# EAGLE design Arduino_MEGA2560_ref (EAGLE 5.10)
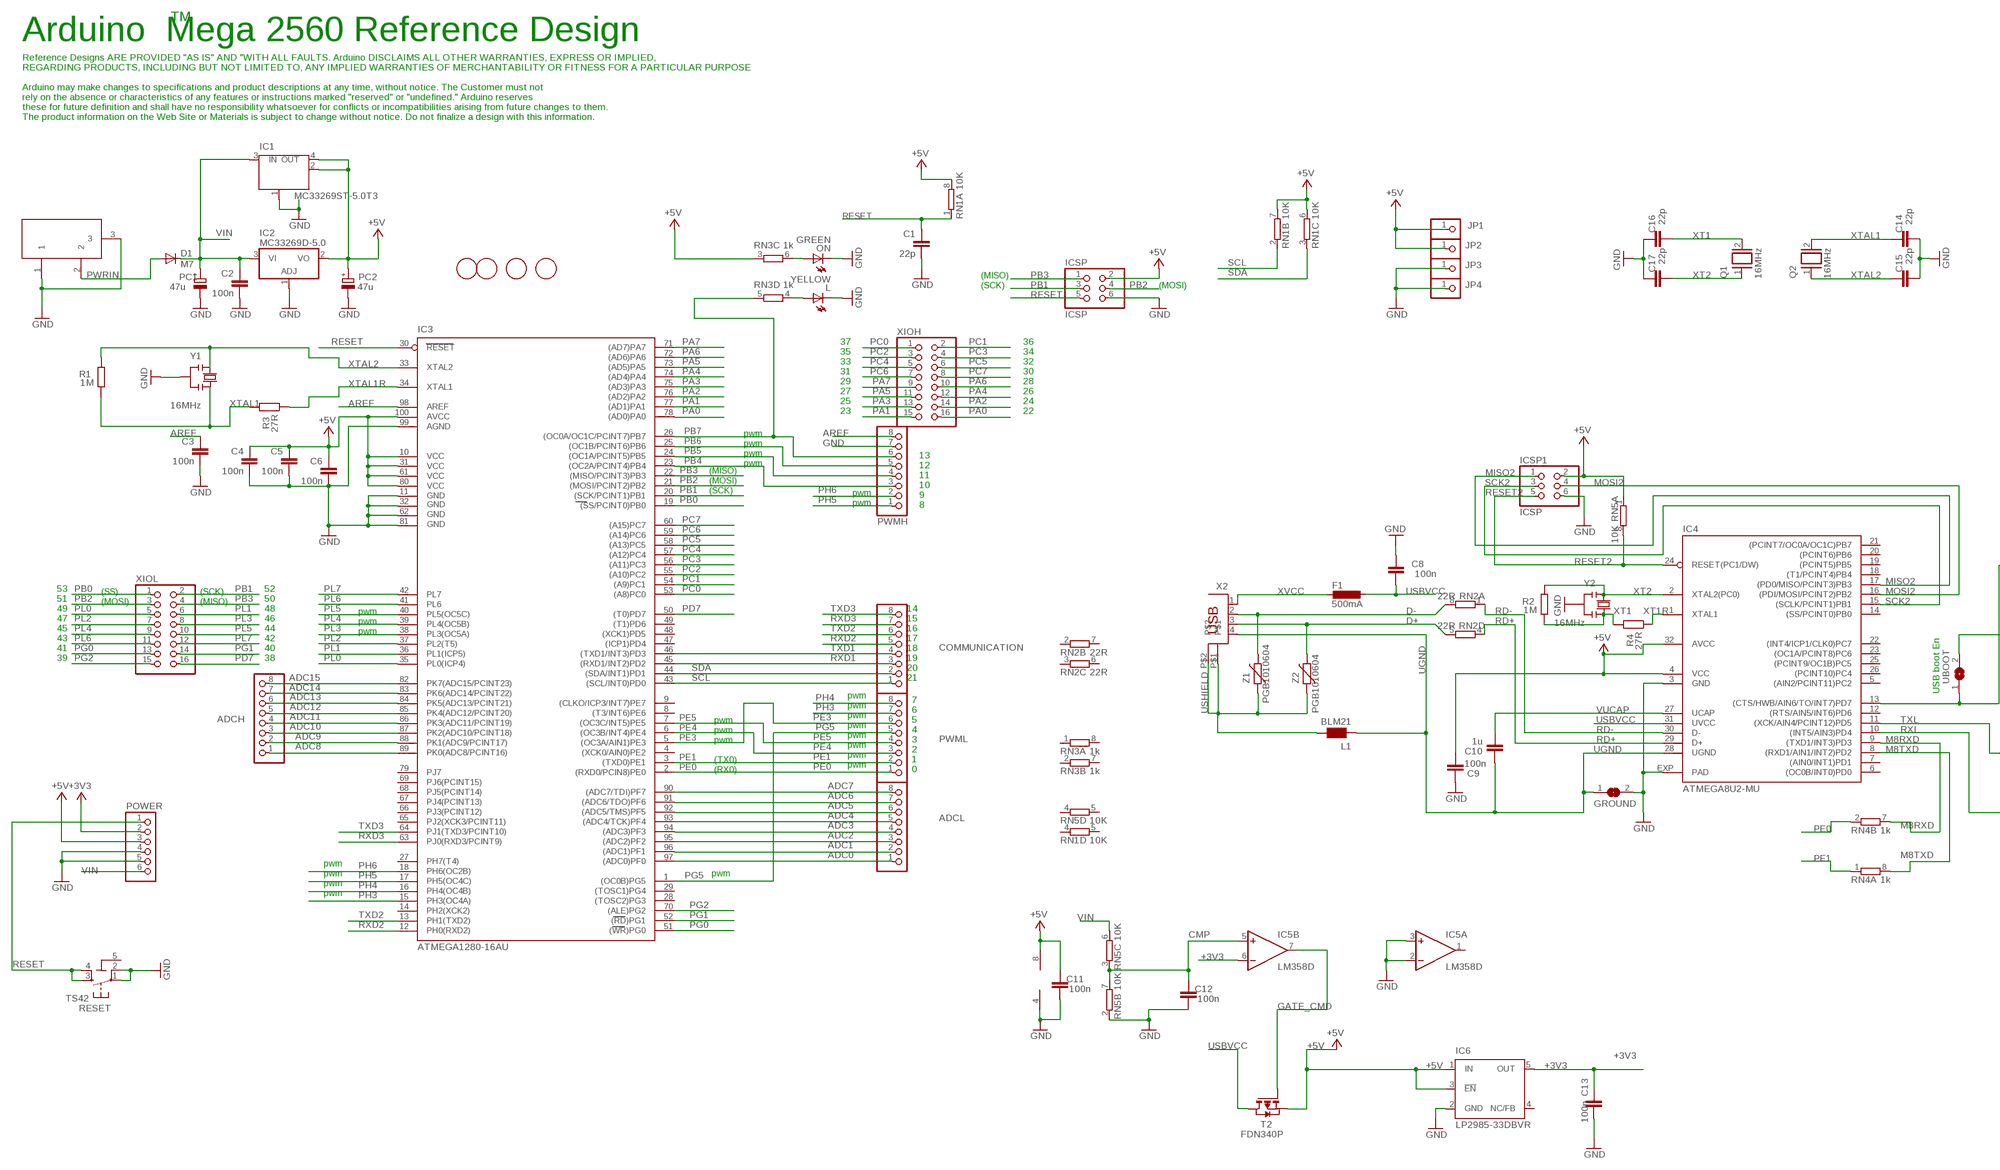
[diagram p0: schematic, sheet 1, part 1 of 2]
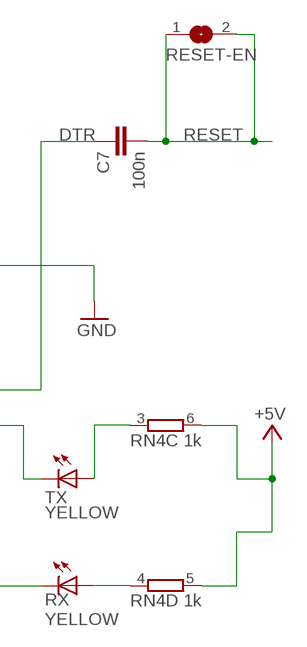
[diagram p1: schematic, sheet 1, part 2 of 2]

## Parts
ADCH  PINHD-1X8  [1X08]
ADCL  PINHD-1X8  [1X08]
C1  22p  C-EU0603-RND  [C0603-ROUND]
C2  100n  C-EU0603-RND  [C0603-ROUND]
C3  100n  C-EU0603-RND  [C0603-ROUND]
C4  100n  C-EU0603-RND  [C0603-ROUND]
C5  100n  C-EU0603-RND  [C0603-ROUND]
C6  100n  C-EU0603-RND  [C0603-ROUND]
C7  100n  C-EU0603-RND  [C0603-ROUND]
C8  100n  C-EUC0603  [C0603]
C9  100n  C-EU0603-RND  [C0603-ROUND]
C10  1u  C-EU0603-RND  [C0603-ROUND]
C11  100n  C-EUC0603  [C0603]
C12  100n  C-EU0603-RND  [C0603-ROUND]
C13  100n  C-EU0603-RND  [C0603-ROUND]
C14  22p  C-EU0603-RND  [C0603-ROUND]
C15  22p  C-EU0603-RND  [C0603-ROUND]
C16  22p  C-EU0603-RND  [C0603-ROUND]
C17  22p  C-EU0603-RND  [C0603-ROUND]
COMMUNICATION  PINHD-1X8  [1X08]
D1  M7  DIODE-SMB  [SMB]
F1  500mA  L-EUL1812  [L1812]
GROUND  SJ  [SJ]
IC1  MC33269ST-5.0T3  MC33269ST-3.3T3  [SOT223]
IC2  MC33269D-5.0  [DPACK]
IC3  ATMEGA1280-16AU  [TQFP100]
IC4  ATMEGA8U2-MU  [QFN32]
IC5  LM358D  [SO08]
IC6  LP2985-33DBVR  TPS77033  [SOT23-DBV]
ICSP  ICSP  PINHD-2X3  [2X03]
ICSP1  ICSP  PINHD-2X3  [2X03]
JP1  PINHD-1X1  [1X01]
JP2  PINHD-1X1  [1X01]
JP3  PINHD-1X1  [1X01]
JP4  PINHD-1X1  [1X01]
L  YELLOW  LEDCHIP-LED0805  [CHIP-LED0805]
L1  BLM21  WE-CBF_0805  [0805]
ON  GREEN  LEDCHIP-LED0805  [CHIP-LED0805]
PC1  47u  CPOL-EUD  [PANASONIC_D]
PC2  47u  CPOL-EUD  [PANASONIC_D]
POWER  PINHD-1X6  [1X06]
PWMH  PINHD-1X8  [1X08]
PWML  PINHD-1X8  [1X08]
Q1  16MHz  XTAL/S  [QS]
Q2  16MHz  XTAL/S  [QS]
R1  1M  R-EU_R0603  [R0603-ROUND]
R2  1M  R-EU_R0603  [R0603-ROUND]
R3  27R  R-EU_R0603  [R0603-ROUND]
R4  27R  R-EU_R0603  [R0603-ROUND]
RESET  TS42  [TS42]
RESET-EN  SJ  [SJ]
RN1  10K  4R-NCAT16  [CAT16]
RN2  22R  4R-NCAY16  [CAY16]
RN3  1k  4R-NCAY16  [CAY16]
RN4  1k  4R-NCAY16  [CAY16]
RN5  10K  4R-NCAT16  [CAT16]
RX  YELLOW  LEDCHIP-LED0805  [CHIP-LED0805]
T2  FDN340P  PMOSSOT23  [SOT-23]
TX  YELLOW  LEDCHIP-LED0805  [CHIP-LED0805]
U$2  FIDUCIALMOUNT  [FIDUCIA-MOUNT]
U$3  FIDUCIALMOUNT  [FIDUCIA-MOUNT]
U$4  FIDUCIALMOUNT  [FIDUCIA-MOUNT]
U$5  FIDUCIALMOUNT  [FIDUCIA-MOUNT]
UBOOT  SJ  [SJ]
X1  DC21MMX  [DC-21MM]
X2  PN61729  [PN61729]
XIOH  PINHD-2X8  [2X08]
XIOL  PINHD-2X8  [2X08]
Y1  16MHz  RESONATORMU  [RESONATOR]
Y2  16MHz  RESONATORMU  [RESONATOR]
Z1  PGB1010604  VARISTORCN0603  [CT/CN0603]
Z2  PGB1010604  VARISTORCN0603  [CT/CN0603]

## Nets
+3V3: C13.2 IC5.6(B:-IN) IC6.5(OUT) POWER.2
+5V: C4.1 C5.1 C6.1 C9.1 C11.2 IC1.2(OUT) IC1.4(OUT) IC2.2(VO) IC3.10(VCC) IC3.31(VCC1) IC3.61(VCC2) IC3.80(VCC3) IC3.100(AVCC) IC4.4(VCC) IC4.32(AVCC) IC5.8(P:V+) IC6.1(IN) IC6.3(!EN) ICSP1.2 ICSP.2 JP1.1 JP2.1 PC2.+ POWER.3 RN1.6 RN1.7 RN1.8 RN3.3 RN4.5 RN4.6 RN5.1 T2.2(S)
ADC0: ADCL.1 IC3.97((ADC0)PF0)
ADC1: ADCL.2 IC3.96((ADC1)PF1)
ADC2: ADCL.3 IC3.95((ADC2)PF2)
ADC3: ADCL.4 IC3.94((ADC3)PF3)
ADC4: ADCL.5 IC3.93((ADC4/TCK)PF4)
ADC5: ADCL.6 IC3.92((ADC5/TMS)PF5)
ADC6: ADCL.7 IC3.91((ADC6/TDO)PF6)
ADC7: ADCL.8 IC3.90((ADC7/TDI)PF7)
ADC8: ADCH.1 IC3.89(PK0(ADC8/PCINT16))
ADC9: ADCH.2 IC3.88(PK1(ADC9/PCINT17))
ADC10: ADCH.3 IC3.87(PK2(ADC10/PCINT18))
ADC11: ADCH.4 IC3.86(PK3(ADC11/PCINT19))
ADC12: ADCH.5 IC3.85(PK4(ADC12/PCINT20))
ADC13: ADCH.6 IC3.84(PK5(ADC13/PCINT21))
ADC14: ADCH.7 IC3.83(PK6(ADC14/PCINT22))
ADC15: ADCH.8 IC3.82(PK7(ADC15/PCINT23))
AREF: C3.1 IC3.98(AREF) PWMH.8
CMP: C12.2 IC5.5(B:+IN) RN5.3 RN5.7
D+: RN2.5 X2.3 Z2.2
D-: RN2.8 X2.2 Z1.2
DTR: C7.1 IC4.13((CTS/HWB/AIN6/TO/INT7)PD7) UBOOT.1
GATE_CMD: IC5.7(B:OUT) T2.3(G)
GND: C1.2 C2.2 C3.2 C4.2 C5.2 C6.2 C8.2 C9.2 C11.1 C12.1 C13.1 C14.1 C15.1 C16.2 C17.2 GROUND.2 IC1.1(GND/ADJ) IC2.1(ADJ) IC3.11(GND) IC3.32(GND1) IC3.62(GND2) IC3.81(GND3) IC3.99(AGND) IC4.3(GND) IC4.EXP(PAD) IC5.2(A:-IN) IC5.3(A:+IN) IC5.4(P:V-) IC6.2(GND) ICSP1.6 ICSP.6 JP3.1 JP4.1 L.C ON.C PC1.- PC2.- POWER.4 POWER.5 PWMH.7 RESET.1 RESET.2 RN5.2 UBOOT.2 X1.1 X1.3 Y1.2 Y2.2
M8RXD: IC4.9((TXD1/INT3)PD3) RN4.7
M8TXD: IC4.8((RXD1/AIN1/INT2)PD2) RN4.8
MISO2: IC4.17((PD0/MISO/PCINT3)PB3) ICSP1.1
MOSI2: IC4.16((PDI/MOSI/PCINT2)PB2) ICSP1.4
N$2: L.A RN3.4
N$3: ON.A RN3.6
N$54: RN4.4 RX.A
N$55: RN4.3 TX.A
PA0: IC3.78((AD0)PA0) XIOH.16
PA1: IC3.77((AD1)PA1) XIOH.15
PA2: IC3.76((AD2)PA2) XIOH.14
PA3: IC3.75((AD3)PA3) XIOH.13
PA4: IC3.74((AD4)PA4) XIOH.12
PA5: IC3.73((AD5)PA5) XIOH.11
PA6: IC3.72((AD6)PA6) XIOH.10
PA7: IC3.71((AD7)PA7) XIOH.9
PB0: IC3.19((SS/PCINT0)PB0) XIOL.1
PB1: IC3.20((SCK/PCINT1)PB1) ICSP.3 XIOL.2
PB2: IC3.21((MOSI/PCINT2)PB2) ICSP.4 XIOL.3
PB3: IC3.22((MISO/PCINT3)PB3) ICSP.1 XIOL.4
PB4: IC3.23((OC2A/PCINT4)PB4) PWMH.3
PB5: IC3.24((OC1A/PCINT5)PB5) PWMH.4
PB6: IC3.25((OC1B/PCINT6)PB6) PWMH.5
PB7: IC3.26((OC0A/OC1C/PCINT7)PB7) PWMH.6 RN3.5
PC0: IC3.53((A8)PC0) XIOH.1
PC1: IC3.54((A9)PC1) XIOH.2
PC2: IC3.55((A10)PC2) XIOH.3
PC3: IC3.56((A11)PC3) XIOH.4
PC4: IC3.57((A12)PC4) XIOH.5
PC5: IC3.58((A13)PC5) XIOH.6
PC6: IC3.59((A14)PC6) XIOH.7
PC7: IC3.60((A15)PC7) XIOH.8
PD7: IC3.50((T0)PD7) XIOL.16
PE0: IC3.2((RXD0/PCIN8)PE0) PWML.1 RN4.2
PE1: IC3.3((TXD0)PE1) PWML.2 RN4.1
PE3: IC3.5((OC3A/AIN1)PE3) PWML.6
PE4: IC3.6((OC3B/INT4)PE4) PWML.3
PE5: IC3.7((OC3C/INT5)PE5) PWML.4
PG0: IC3.51((WR)PG0) XIOL.13
PG1: IC3.52((RD)PG1) XIOL.14
PG2: IC3.70((ALE)PG2) XIOL.15
PG5: IC3.1((OC0B)PG5) PWML.5
PH3: IC3.15(PH3(OC4A)) PWML.7
PH4: IC3.16(PH4(OC4B)) PWML.8
PH5: IC3.17(PH5(OC4C)) PWMH.1
PH6: IC3.18(PH6(OC2B)) PWMH.2
PL0: IC3.35(PL0(ICP4)) XIOL.5
PL1: IC3.36(PL1(ICP5)) XIOL.6
PL2: IC3.37(PL2(T5)) XIOL.7
PL3: IC3.38(PL3(OC5A)) XIOL.8
PL4: IC3.39(PL4(OC5B)) XIOL.9
PL5: IC3.40(PL5(OC5C)) XIOL.10
PL6: IC3.41(PL6) XIOL.11
PL7: IC3.42(PL7) XIOL.12
PWRIN: D1.A X1.2
RD+: IC4.29(D+) RN2.4
RD-: IC4.30(D-) RN2.1
RESET: C1.1 C7.2 IC3.30(RESET) ICSP.5 POWER.1 RESET-EN.1 RESET-EN.2 RESET.3 RESET.4 RN1.1
RESET2: IC4.24(RESET(PC1/DW)) ICSP1.5 RN5.8
RXD1: COMMUNICATION.3 IC3.45((RXD1/INT2)PD2)
RXD2: COMMUNICATION.5 IC3.12(PH0(RXD2))
RXD3: COMMUNICATION.7 IC3.63(PJ0(RXD3/PCINT9))
RXL: IC4.10((INT5/AIN3)PD4) RX.C
SCK2: IC4.15((SCLK/PCINT1)PB1) ICSP1.3
SCL: COMMUNICATION.1 IC3.43((SCL/INT0)PD0) RN1.2
SDA: COMMUNICATION.2 IC3.44((SDA/INT1)PD1) RN1.3
TXD1: COMMUNICATION.4 IC3.46((TXD1/INT3)PD3)
TXD2: COMMUNICATION.6 IC3.13(PH1(TXD2))
TXD3: COMMUNICATION.8 IC3.64(PJ1(TXD3/PCINT10))
TXL: IC4.11((XCK/AIN4/PCINT12)PD5) TX.C
UGND: C10.2 GROUND.1 IC4.28(UGND) L1.1 X2.4
USBVCC: C8.1 F1.1 IC4.31(UVCC) T2.1(D)
USHIELD: L1.2 X2.P$1 X2.P$2 Z1.1 Z2.1
VIN: C2.1 D1.C IC1.3(IN) IC2.3(VI) PC1.+ POWER.6 RN5.6
VUCAP: C10.1 IC4.27(UCAP)
XT1: C16.1 Q1.2 R2.1 R4.2 Y2.3
XT1R: IC4.1(XTAL1) R4.1
XT2: C17.1 IC4.2(XTAL2(PC0)) Q1.1 R2.2 Y2.1
XTAL1: C14.2 Q2.2 R1.1 R3.2 Y1.3
XTAL1R: IC3.34(XTAL1) R3.1
XTAL2: C15.2 IC3.33(XTAL2) Q2.1 R1.2 Y1.1
XVCC: F1.2 X2.1
Unconnected: IC3.4((XCK0/AIN0)PE2) IC3.8((T3/INT6)PE6) IC3.9((CLKO/ICP3/INT7)PE7) IC3.14(PH2(XCK2)) IC3.27(PH7(T4)) IC3.28((TOSC2)PG3) IC3.29((TOSC1)PG4) IC3.47((ICP1)PD4) IC3.48((XCK1)PD5) IC3.49((T1)PD6) IC3.65(PJ2(XCK3/PCINT11)) IC3.66(PJ3(PCINT12)) IC3.67(PJ4(PCINT13)) IC3.68(PJ5(PCINT14)) IC3.69(PJ6(PCINT15)) IC3.79(PJ7) IC4.5((AIN2/PCINT11)PC2) IC4.6((OC0B/INT0)PD0) IC4.7((AIN0/INT1)PD1) IC4.12((RTS/AIN5/INT6)PD6) IC4.14((SS/PCINT0)PB0) IC4.18((T1/PCINT4)PB4) IC4.19((PCINT5)PB5) IC4.20((PCINT6)PB6) IC4.21((PCINT7/OC0A/OC1C)PB7) IC4.22((INT4/ICP1/CLK0)PC7) IC4.23((OC1A/PCINT8)PC6) IC4.25((PCINT9/OC1B)PC5) IC4.26((PCINT10)PC4) IC5.1(A:OUT) IC6.4(NC/FB) RN1.4 RN1.5 RN2.2 RN2.3 RN2.6 RN2.7 RN3.1 RN3.2 RN3.7 RN3.8 RN5.4 RN5.5

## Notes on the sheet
- TM
- Arduino  Mega 2560 Reference Design
- Reference Designs ARE PROVIDED "AS IS" AND "WITH ALL FAULTS. Arduino DISCLAIMS ALL OTHER WARRANTIES, EXPRESS OR IMPLIED,
- REGARDING PRODUCTS, INCLUDING BUT NOT LIMITED TO, ANY IMPLIED WARRANTIES OF MERCHANTABILITY OR FITNESS FOR A PARTICULAR PURPOSE
- Arduino may make changes to specifications and product descriptions at any time, without notice. The Customer must not
- rely on the absence or characteristics of any features or instructions marked "reserved" or "undefined." Arduino reserves
- these for future definition and shall have no responsibility whatsoever for conflicts or incompatibilities arising from future changes to them.
- The product information on the Web Site or Materials is subject to change without notice. Do not finalize a design with this information.
- (MISO)
- (SCK) | (MOSI)
- 37 | 36
- 35 | 34
- 33 | 32
- 31 | 30
- 29 | 28
- 27 | 26
- 25 | 24
- 23 | 22
- pwm
- pwm
- pwm | 13
- pwm | 12
- (MISO)
- 11
- (MOSI)
- 10
- (SCK) | pwm
- 9
- pwm | 8
- 53 | (SS) | (SCK) | 52
- 51 | (MOSI) | (MISO) | 50
- 49 | 48 | pwm | 14
- 47 | 46 | pwm | 15
- 45 | 44 | pwm | 16
- 43 | 42 | 17
- 41 | 40 | 18
- 39 | 38 | 19
- 20
- 21
- USB boot En
- pwm
- 7
- pwm
- 6
- pwm
- pwm | 5
- pwm
- pwm | 4
- pwm
- pwm | 3
- pwm
- 2
- pwm
- (TX0) | 1
- pwm
- (RX0) | 0
- pwm
- pwm | pwm
- pwm
- pwm

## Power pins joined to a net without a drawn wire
5-GND: RESET.5(5-GND)

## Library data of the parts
ADCH ADCL COMMUNICATION PWMH PWML = pinhead:PINHD-1X8: PIN HEADER
C1-C7 C9 C10 C12-C17 = SmartPrj:C-EU: CAPACITOR, European symbol
C8 C11 = rcl:C-EU: CAPACITOR, European symbol
D1 = diode:DIODE-: DIODE
F1 = rcl:L-EU: INDUCTOR, European symbol
GROUND RESET-EN UBOOT = jumper:SJ: SMD solder JUMPER
IC1 = linear:MC33269ST*: Adjustable Output Low Dropout Voltage Regulator 800 mA Source: http://www.onsemi.com/pub/Collateral/MC33269-D.PDF
IC2 = linear:MC33269?*: Adjustable Output Low Dropout Voltage Regulator 800 mA Source: http://www.onsemi.com/pub/Collateral/MC33269-D.PDF
IC3 = atmel-2005:ATMEGA*: MICROCONTROLLER 64/128/256 Kbytes FLASH 4 Kbytes EEPROM 8 Kbytes SRAM 86 General Purpose I/O pins 12-channels16-bit PWM 4 x Serial USARTs 16-channels 10-bit A/D
IC4 = atmel:ATMEGA8U2-MU
IC5 = linear:LM358: OP AMP also LM158; LM258; LM2904 Source: http://cache.national.com/ds/LM/LM158.pdf
IC6 = texas:TPS770*: ULTRALOW-POWER 50-mA LOW-DROPOUT LINEAR REGULATORS 50-mA Low-Dropout Regulator Source: http://focus.ti.com/lit/ds/symlink/tps77001.pdf
ICSP ICSP1 = pinhead:PINHD-2X3: PIN HEADER
JP1-JP4 = pinhead:PINHD-1X1: PIN HEADER
L ON RX TX = led:LED: LED
L1 = wuerth-elektronik:WE-CBF: SMD EMI Suppression Ferrite Beads
PC1 PC2 = rcl:CPOL-EU: POLARIZED CAPACITOR, European symbol
POWER = pinhead:PINHD-1X6: PIN HEADER
Q1 Q2 = special:XTAL/S: CRYSTAL
R1-R4 = SmartPrj:R-EU_: RESISTOR, European symbol
RESET = st-mod v1.4:TS42: TS42 Dongnan Electronics Tact switch VDC 12V - 50mA
RN1-RN5 = resistor-dil:4R-N: Array Chip Resistor Source: RS Component / Phycomp
T2 = zetex:PMOSSOT23: MOS FET
U$2-U$5 = SmartPrj:FIDUCIALMOUNT
X1 = powersupply:DC21MM
X2 = SmartPrj:PN61729: BERG USB connector
XIOH XIOL = pinhead:PINHD-2X8: PIN HEADER
Y1 Y2 = SmartPrj:RESONATOR
Z1 Z2 = varistor:VARISTOR: VARISTOR

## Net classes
0 default: width 0.152 mm, drill 0.305 mm, clearance 0.152 mm

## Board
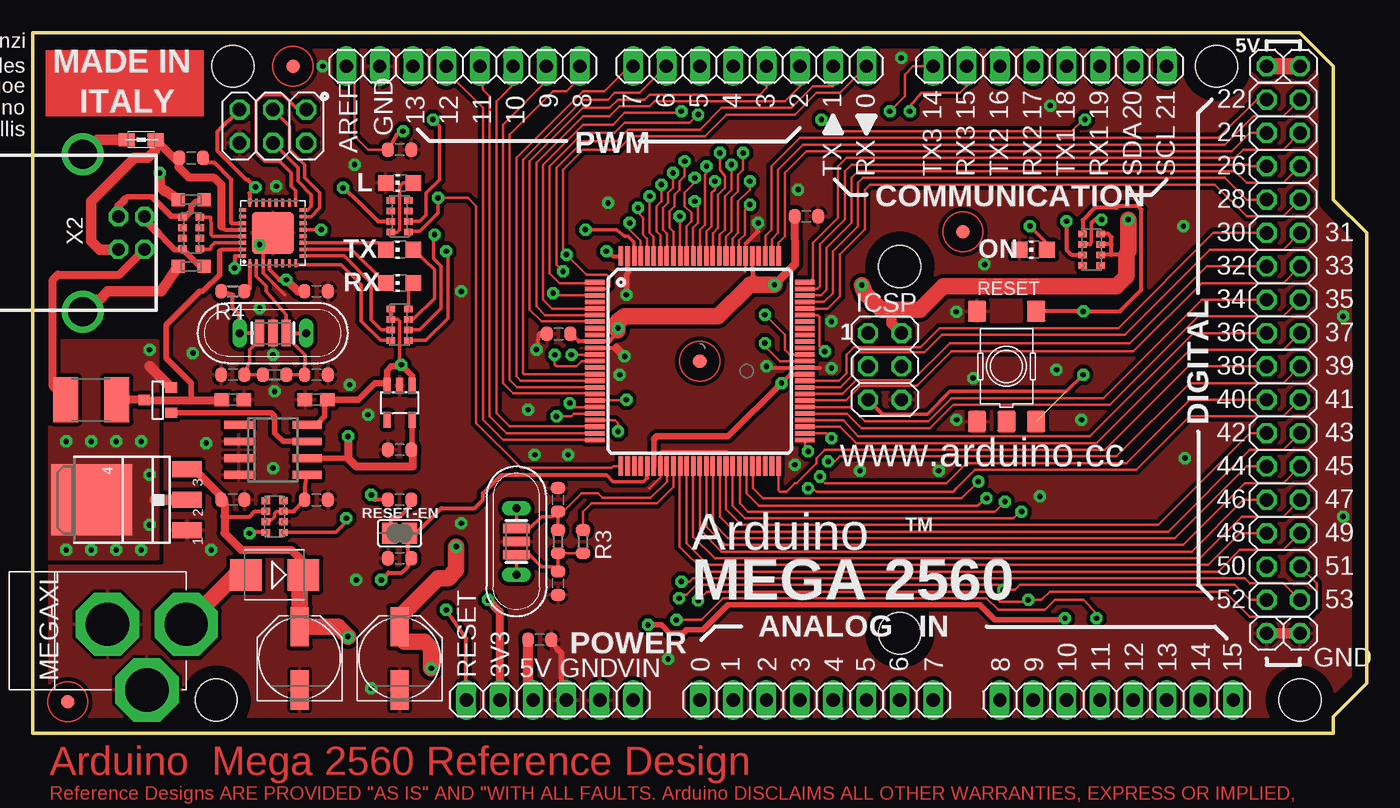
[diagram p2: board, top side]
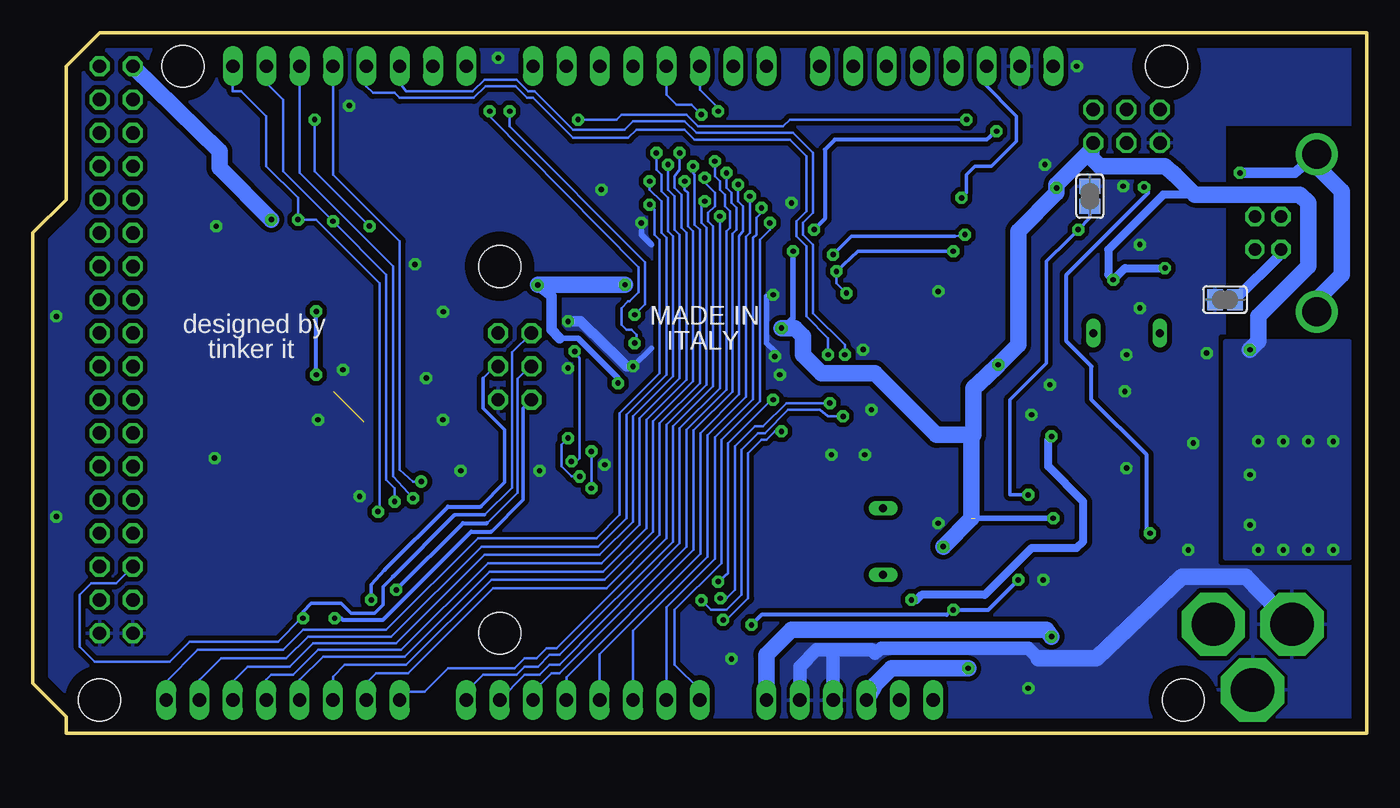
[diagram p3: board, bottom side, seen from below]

Size 101.6 x 53.34 mm. Coordinates in mm from the lower left corner, seen from the top.
Outline: 0,53.34 96.52,53.34 99.06,50.8 99.06,40.64 101.6,38.1 101.6,3.81 99.06,1.27 99.06,0 0,0 0,53.34
Copper layers (1*16): Top 0.035mm / dielectric 1.5mm / Bottom 0.035mm
Design rules "default *": minimum track width 6mil, minimum drill 12mil, track to track 6mil, track to pad 6mil, pad to pad 6mil, via to via 6mil, smd to smd 6mil, copper to edge 40mil, drill to drill 12mil, minimum pad ring 10mil, minimum via ring 10mil, stop-mask expansion 2mil, vias tented up to drill 1mil, thermal gap 10mil
Holes 3.2 mm at 96.52,2.54 15.24,50.8 90.17,50.8 13.97,2.54 66.04,35.56 66.04,7.62

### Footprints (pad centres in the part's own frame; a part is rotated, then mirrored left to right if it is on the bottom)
1X08 = drill 1.016 long: 1 -8.89,0; 2 -6.35,0; 3 -3.81,0; 4 -1.27,0; 5 1.27,0; 6 3.81,0; 7 6.35,0; 8 8.89,0
C0603-ROUND = smd 0.898 x 1.1: 1 -0.889,0; 2 0.889,0
C0603 = smd 1.1 x 1: 1 -0.85,0; 2 0.85,0
SMB = smd 2.4 x 2.4: A 2.2,0; C -2.2,0
L1812 = smd 1.9 x 3.4: 1 -1.95,0; 2 1.95,0
SJ = smd 1.168 x 1.6: 1 -0.762,0; 2 0.762,0
SOT223 = smd 1.219 x 2.235: 1 -2.311,-3.099; 2 0,-3.099; 3 2.311,-3.099 | smd 3.6 x 2.2: 4 0,3.099
DPACK = smd 1 x 1.6: 1 -2.28,-4.8; 3 2.28,-4.8 | smd 5.4 x 6.2: 2 0,2.5
TQFP100 = smd 1.5 x 0.35: 1 -8,6; 2 -8,5.5; 3 -8,5; 4 -8,4.5; 5 -8,4; 6 -8,3.5; 7 -8,3; 8 -8,2.5; 9 -8,2; 10 -8,1.5; 11 -8,1; 12 -8,0.5; 13 -8,0; 14 -8,-0.5; 15 -8,-1; 16 -8,-1.5; 17 -8,-2; 18 -8,-2.5; 19 -8,-3; 20 -8,-3.5; 21 -8,-4; 22 -8,-4.5; 23 -8,-5; 24 -8,-5.5; 25 -8,-6; 51 8,-6; 52 8,-5.5; 53 8,-5; 54 8,-4.5; 55 8,-4; 56 8,-3.5; 57 8,-3; 58 8,-2.5; 59 8,-2; 60 8,-1.5; 61 8,-1; 62 8,-0.5; 63 8,0; 64 8,0.5; 65 8,1; 66 8,1.5; 67 8,2; 68 8,2.5; 69 8,3; 70 8,3.5; 71 8,4; 72 8,4.5; 73 8,5; 74 8,5.5; 75 8,6 | smd 0.35 x 1.5: 26 -6,-8; 27 -5.5,-8; 28 -5,-8; 29 -4.5,-8; 30 -4,-8; 31 -3.5,-8; 32 -3,-8; 33 -2.5,-8; 34 -2,-8; 35 -1.5,-8; 36 -1,-8; 37 -0.5,-8; 38 0,-8; 39 0.5,-8; 40 1,-8; 41 1.5,-8; 42 2,-8; 43 2.5,-8; 44 3,-8; 45 3.5,-8; 46 4,-8; 47 4.5,-8; 48 5,-8; 49 5.5,-8; 50 6,-8; 76 6,8; 77 5.5,8; 78 5,8; 79 4.5,8; 80 4,8; 81 3.5,8; 82 3,8; 83 2.5,8; 84 2,8; 85 1.5,8; 86 1,8; 87 0.5,8; 88 0,8; 89 -0.5,8; 90 -1,8; 91 -1.5,8; 92 -2,8; 93 -2.5,8; 94 -3,8; 95 -3.5,8; 96 -4,8; 97 -4.5,8; 98 -5,8; 99 -5.5,8; 100 -6,8
QFN32 = smd 0.6 x 0.3: 1 -2.3,1.75; 2 -2.3,1.25; 3 -2.3,0.75; 4 -2.3,0.25; 5 -2.3,-0.25; 6 -2.3,-0.75; 7 -2.3,-1.25; 8 -2.3,-1.75; 17 2.3,-1.75; 18 2.3,-1.25; 19 2.3,-0.75; 20 2.3,-0.25; 21 2.3,0.25; 22 2.3,0.75; 23 2.3,1.25; 24 2.3,1.75 | smd 0.3 x 0.6: 9 -1.75,-2.3; 10 -1.25,-2.3; 11 -0.75,-2.3; 12 -0.25,-2.3; 13 0.25,-2.3; 14 0.75,-2.3; 15 1.25,-2.3; 16 1.75,-2.3; 25 1.75,2.3; 26 1.25,2.3; 27 0.75,2.3; 28 0.25,2.3; 29 -0.25,2.3; 30 -0.75,2.3; 31 -1.25,2.3; 32 -1.75,2.3 | smd 3.2 x 3.2: EXP 0,0
SO08 = smd 0.6 x 2.2: 1 -1.905,-2.6; 2 -0.635,-2.6; 3 0.635,-2.6; 4 1.905,-2.6; 5 1.905,2.6; 6 0.635,2.6; 7 -0.635,2.6; 8 -1.905,2.6
SOT23-DBV = smd 0.55 x 1.2: 1 -0.95,-1.3; 2 0,-1.3; 3 0.95,-1.3; 4 0.95,1.3; 5 -0.95,1.3
2X03 = drill 1.016 octagon: 1 -2.54,-1.27; 2 -2.54,1.27; 3 0,-1.27; 4 0,1.27; 5 2.54,-1.27; 6 2.54,1.27
1X01 = drill 1.016 octagon: 1 0,0
CHIP-LED0805 = smd 1.2 x 1.2: A 0,-1.05; C 0,1.05
0805 = smd 1.2 x 1: 1 -1.1,0; 2 1.1,0
PANASONIC_D = smd 3 x 1.4: + 2.4,0; - -2.4,0
1X06 = drill 1.016 long: 1 -6.35,0; 2 -3.81,0; 3 -1.27,0; 4 1.27,0; 5 3.81,0; 6 6.35,0
QS = drill 0.61 long: 1 -2.54,0; 2 2.54,0
R0603-ROUND = smd 0.898 x 1.1: 1 -0.889,0; 2 0.889,0
TS42 = smd 1.6 x 1.4: 1 -4.2,2.25; 2 4.2,2.25; 3 -4.2,-2.25; 4 4.2,-2.25; 5 -4.2,0
CAT16 = smd 0.5 x 0.65: 1 -1.2,-0.675; 2 -0.4,-0.675; 3 0.4,-0.675; 4 1.2,-0.675; 5 1.2,0.675; 6 0.4,0.675; 7 -0.4,0.675; 8 -1.2,0.675
CAY16 = smd 0.5 x 0.65: 1 -1.2,-0.675; 2 -0.4,-0.675; 3 0.4,-0.675; 4 1.2,-0.675; 5 1.2,0.675; 6 0.4,0.675; 7 -0.4,0.675; 8 -1.2,0.675
SOT-23 = smd 0.787 x 0.889: 1 0.025,-1.016; 2 -0.94,1.016; 3 0.991,1.016
FIDUCIA-MOUNT = smd 1.016 x 1.016: P$1 0,0
DC-21MM = drill 3.302 pad 4.826 octagon: 1 -5.08,-3.353; 2 -0.076,-6.35; 3 -0.076,-0.356
PN61729 = drill 0.95 octagon: 1 1.25,4.71; 2 -1.25,4.71; 3 -1.25,2.71; 4 1.25,2.71 | drill 2.2 round: P$1 -6,0; P$2 6,0
2X08 = drill 1.016 octagon: 1 -8.89,-1.27; 2 -8.89,1.27; 3 -6.35,-1.27; 4 -6.35,1.27; 5 -3.81,-1.27; 6 -3.81,1.27; 7 -1.27,-1.27; 8 -1.27,1.27; 9 1.27,-1.27; 10 1.27,1.27; 11 3.81,-1.27; 12 3.81,1.27; 13 6.35,-1.27; 14 6.35,1.27; 15 8.89,-1.27; 16 8.89,1.27
RESONATOR = smd 0.7 x 2: 1 -1,0; 2 0,0; 3 1,0
CT/CN0603 = smd 1 x 1: 1 -1,0; 2 1,0

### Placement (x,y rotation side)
ADCH  82.55,2.54 0 top
ADCL  59.69,2.54 0 top
C1  27.94,13.34 180 top
C2  15.24,17.78 0 top
C3  27.94,44.45 0 top
C4  38.61,7.11 0 top
C5  58.93,39.37 0 top
C6  40.05,30.42 180 top
C7  27.94,17.78 0 top
C8  15.24,25.4 0 top
C9  21.59,33.66 0 top
C10  12.06,43.81 180 top
C11  21.59,25.4 0 top
C12  21.59,17.78 180 top
C13  27.94,21.59 0 top
C14  40.01,11.43 90 top
C15  40.01,17.78 270 top
C16  15.24,27.3 180 top
C17  21.59,27.3 0 top
COMMUNICATION  77.47,50.8 180 top
D1  18.41,12.06 180 top
F1  4.45,25.4 180 top
GROUND  10.79,33.02 180 bottom
IC1  8.64,17.78 90 top
IC2  6.99,17.78 90 top
IC3  50.8,28.35 0 top
IC4  18.29,38.1 90 top
IC5  18.29,21.59 270 top
IC6  27.94,25.17 180 top
ICSP  64.9,27.94 270 top
ICSP1  18.29,46.23 180 top
JP1  93.98,50.8 0 top
JP2  96.52,50.8 0 top
JP3  93.98,7.62 0 top
JP4  96.52,7.62 0 top
L  27.94,41.91 90 top
L1  8.26,45.21 180 top
ON  76.2,36.83 90 top
PC1  20.32,5.71 90 top
PC2  27.94,5.71 90 top
POWER  39.37,2.54 0 top
PWMH  32.77,50.8 180 top
PWML  54.61,50.8 180 top
Q1  18.29,30.48 180 top
Q2  36.83,14.61 270 top
R1  40.01,14.61 90 top
R2  18.41,27.3 0 top
R3  41.91,14.61 270 top
R4  15.24,33.66 180 top
RESET  74.17,27.94 90 top
RESET-EN  27.94,15.24 0 top
RN1  80.64,36.83 270 top
RN2  12.06,38.1 90 top
RN3  27.94,39.37 270 top
RN4  27.94,31.11 90 top
RN5  18.41,16.51 90 top
RX  27.94,34.29 90 top
T2  9.53,25.4 270 top
TX  27.94,36.83 90 top
U$2  70.84,38.19 0 top
U$3  2.67,2.41 0 top
U$4  19.81,50.8 0 top
U$5  50.8,28.35 0 top
UBOOT  21.08,40.89 90 bottom
X1  5.33,8.38 90 top
X2  3.81,38.1 270 top
XIOH  95.25,39.37 90 top
XIOL  95.25,19.05 90 top
Y1  36.83,14.61 270 top
Y2  18.29,30.48 180 top
Z1  12.06,35.56 0 top
Z2  12.06,40.64 0 top

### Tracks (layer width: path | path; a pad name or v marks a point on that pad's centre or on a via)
+3V3  (via drill 0.41)
  Top 0.406: 28.89,21.62 IC6.5 | 24,20.95 IC5.6
  Top 0.61: POWER.2 35.56,9.27 v34.67,10.16 | 28.89,21.62 C13.2 28.96,21.55 28.96,20.32 24.64,20.32 24,20.95 v24,22.61
  Bottom 0.61: v34.67,10.16 34.29,10.16 33.91,10.54 29.08,10.54 25.53,14.1 22.1,14.1 21.59,14.61 21.59,17.65 24.26,20.32 24.26,22.35 v24,22.61
+5V  (via drill 0.41)  (1 unrouted)
  Top 0.254: IC3.80 54.81,36.3 54.79,36.27 54.81,36.25 54.81,35.41 | 57.66,27.3 57.7,27.35 | v28.07,28.07 28,28.19 27.94,28.64 27.94,31.37 27.79,31.52 RN4.6 RN4.5 | v23.88,16.38 23.88,16.13 23.06,15.31 RN5.1
  Top 0.305: 54.86,34.67 54.86,35.1 54.81,35.15 54.81,35.41 | 57.7,27.35 IC3.61 | v57.02,26.67 57.66,27.3 | 44.45,30.48 43.94,29.85 IC3.10 41.59,29.85 C6.1 | IC3.100 44.17,36.35 v43.69,36.7 | IC4.32 15.39,36.35 v15.37,35.43 | IC4.4 18.04,35.3 18.8,34.54 | RN1.8 81.92,38.03 82.17,37.78 82.17,37.21 | 83.31,36.45 82.17,36.45 | v23.62,41.53 24.89,40.39 26.29,38.99 27.25,38.99 RN3.3 | RN1.6 82.15,36.43 82.17,36.45 | 82.17,36.45 82.17,37.21 | RN1.7 82.15,37.23 82.17,37.21
  Top 0.406: 44.55,30.7 44.45,30.48 v44.58,30.86 | 47.3,22.41 IC3.31 | IC5.8 21.65,23.55 22.23,24.13 22.23,25.18 C11.2 | v19.3,34.54 18.8,34.54
  Top 0.508: 47.3,22.41 47.5,22.61 52.96,22.61 v57.02,26.67 | C11.2 24.77,25.4 26.04,26.67 26.96,26.67 IC6.3 26.99,27.62 27.3,27.94 27.94,27.94 | IC6.1 28.89,27.24 v28.07,28.07
  Top 0.61: v28.07,28.07 27.94,27.94 | 54.86,34.67 54.86,34.29 54.99,34.16 | C5.1 58.08,35.75 v56.49,34.16 | C9.1 20.19,33.66 v19.3,34.54
  Top 0.813: 9.27,17.78 IC1.2 | C4.1 37.72,3.94 POWER.3 | 83.31,34.8 83.31,34.92 | 65.41,32.26 65.41,31.24 ICSP.2 | T2.2 10.49,26.34 8.89,27.94
  Top 1.27: JP1.1 JP2.1 | v63.14,34.14 63.37,33.53 64.64,32.26 65.41,32.26 67.56,32.26 69.34,34.04 82.55,34.04 83.31,34.8 | 83.31,34.92 83.31,36.45 83.44,36.7 v83.44,39.12 | 44.55,30.7 44.55,31.34 45.09,31.75 52.2,31.75 54.61,34.16 54.99,34.16 v56.49,34.16 | v32.26,14.22 32.26,12.45 31.62,11.81 30.86,11.81 27.94,8.89 PC2.+ 27.94,7.37 28.32,6.99 29.84,6.99 30.35,6.48 v30.35,4.95
  Bottom 0.254: 23.62,41.78 23.88,41.53
  Bottom 0.305: 15.37,43.18 14.48,43.05 | 23.88,41.53 v23.62,41.53
  Bottom 0.406: v44.58,30.86 44.58,30.73 43.69,31.62 v43.69,36.7 | 61.47,30.1 60.07,30.1 57.02,27.05 v57.02,26.67 | v23.88,16.38 29.84,16.38
  Bottom 0.61: 63.12,34.16 v63.14,34.14 | 13.08,41.02 15.49,41.02 19.68,36.83 19.68,34.92 v19.3,34.54 18.41,35.43 v15.37,35.43
  Bottom 0.813: 61.47,30.1 62.1,30.73 62.1,33.27 v63.14,34.14
  Bottom 1.27: v30.35,4.95 36.2,4.95 37.47,3.68 POWER.3 | v56.49,34.16 63.12,34.16 | v44.58,30.86 43.56,30.86 42.93,30.23 42.93,28.83 41.53,27.43 37.47,27.43 32.77,22.73 30.1,22.73 | JP1.1 87.38,44.32 87.38,43.05 v83.44,39.12 | 20.95,44.45 20.95,43.81 20.32,43.18 15.37,43.18 14.61,42.55 13.08,41.02 5.08,41.02 4.45,40.39 4.45,35.56 8.26,31.75 8.26,29.84 v8.89,29.21 | 20.95,44.45 20.95,44.83 ICSP1.2 | 20.95,44.45 23.62,41.78 23.62,41.15 26.54,38.23 26.54,29.59 v28.07,28.07 28.96,27.18 29.97,26.29 29.97,22.73 30.1,22.73 | 30.1,22.73 30.1,16.38 v32.26,14.22
  other vias: 6.35,22.23 4.45,22.23 8.26,22.23 2.54,22.23 8.89,19.68 2.54,13.97 6.35,13.97 4.45,13.97 8.89,15.88 8.26,13.97
  pour Top (isolate 0.305, no thermals): 9.53,13.34 9.53,29.84 0.64,29.84 0.64,13.34
  pour Bottom: 1.27,13.34 1.27,29.84 10.79,29.84 10.79,13.34
ADC0  (via drill 0.41)
  Top 0.203: IC3.97 46.3,37.52 45.47,38.35 v45.47,38.86
  Bottom 0.203: ADCL.1 50.8,3.3 52.7,5.21 52.7,9.4 49.15,12.95 49.15,22.35 46.23,25.27 46.23,37.59 45.47,38.35 v45.47,38.86
ADC1  (via drill 0.41)
  Top 0.203: IC3.96 46.8,37.66 46.48,37.97 46.48,39.24 46.1,39.62 v46.1,40.01
  Bottom 0.203: ADCL.2 53.34,9.6 49.63,13.31 49.63,22.55 46.74,25.45 46.74,37.72 46.48,37.97 46.48,39.24 46.1,39.62 v46.1,40.01
ADC2  (via drill 0.41)
  Top 0.203: v46.99,40.89 46.99,38.1 47.27,37.82 47.27,36.68 47.37,36.58 47.3,36.51 47.3,36.38 47.27,36.35 | 47.27,36.35 47.24,36.32 | 47.27,36.35 IC3.95
  Bottom 0.203: ADCL.3 55.88,7.8 50.22,13.46 50.22,22.68 47.27,25.63 47.27,37.82 46.99,38.1 v46.99,40.89
ADC3  (via drill 0.41)
  Top 0.203: IC3.94 47.8,37.92 47.5,38.23 47.5,40.13 47.88,40.51 v47.88,41.78
  Bottom 0.203: ADCL.4 58.42,2.74 58.52,2.85 58.52,3.05 58.42,3.15 58.42,6.02 50.75,13.69 50.75,22.86 47.8,25.81 47.8,37.85 47.75,37.97 47.5,38.23 47.5,40.13 47.88,40.51 v47.88,41.78
ADC4  (via drill 0.41)
  Top 0.203: IC3.93 48.3,38.06 48.01,38.35 48.01,40.01 48.39,40.39 48.39,41.15 48.77,41.53 v48.77,42.67
  Bottom 0.203: 60.96,2.44 ADCL.5 60.96,4.27 51.26,13.97 51.26,23.06 48.31,26.01 48.31,38.05 48.01,38.35 48.01,40.01 48.39,40.39 48.39,41.15 48.77,41.53 v48.77,42.67
ADC5  (via drill 0.41)
  Top 0.203: IC3.92 48.8,38.2 48.51,38.48 48.51,39.75 48.9,40.13 48.9,41.02 49.28,41.4 49.28,42.04 49.66,42.42 v49.66,43.56
  Bottom 0.203: v49.66,43.56 49.66,42.42 49.28,42.04 49.28,41.4 48.9,41.02 48.9,40.13 48.51,39.75 48.51,38.48 48.77,38.23 48.77,26.16 51.82,23.11 51.82,14.22 61.47,4.57 62.1,4.57 63.5,3.17 ADCL.6
ADC6  (via drill 0.41)
  Top 0.203: IC3.91 49.3,39.35 v49.28,39.37
  Bottom 0.203: v49.28,39.37 49.28,26.29 52.32,23.24 52.32,14.48 61.47,5.21 62.23,5.21 62.99,4.45 64.14,4.45 ADCL.7
ADC7  (via drill 0.41)
  Top 0.203: IC3.90 49.8,38.62 50.16,38.99 50.16,39.62 49.66,40.13 49.66,41.15 50.42,41.91 v50.42,42.29
  Bottom 0.203: v50.42,42.29 50.42,41.91 49.66,41.15 49.66,40.13 50.16,39.62 50.16,38.99 49.78,38.61 49.78,26.42 52.83,23.37 52.83,14.61 61.47,5.97 62.23,5.97 63.12,5.08 64.14,5.08 64.77,4.45 67.31,4.45 68.58,3.17 | 68.58,3.17 ADCL.8 | 68.58,3.17 68.58,3.94
ADC8  (via drill 0.41)
  Top 0.203: IC3.89 50.3,38.49 50.67,38.86 50.67,40.26 v50.42,40.51
  Bottom 0.203: v50.42,40.51 50.67,40.26 50.67,38.86 50.29,38.48 50.29,26.54 53.34,23.5 53.34,14.86 61.72,6.48 62.48,6.48 63.25,5.71 64.14,5.71 64.9,4.95 69.98,4.95 71.75,3.17 73.66,3.17 ADCH.1
ADC9  (via drill 0.41)
  Top 0.203: IC3.88 50.8,38.35 51.18,38.73 51.18,42.55 51.31,42.67 v51.31,43.18
  Bottom 0.203: v51.31,43.18 51.31,42.67 51.18,42.55 51.18,38.73 50.8,38.35 50.8,26.67 53.85,23.62 53.85,15.11 57.91,11.05 66.55,11.05 73.03,4.57 75.44,4.57 76.2,3.81 ADCH.2
ADC10  (via drill 0.41)
  Top 0.203: IC3.87 51.3,38.22 51.69,38.61 51.69,41.15 51.94,41.4 v51.94,42.04
  Bottom 0.203: v51.94,42.04 51.94,41.4 51.69,41.15 51.69,38.61 51.31,38.23 51.31,26.8 54.36,23.75 54.36,15.37 58.04,11.68 66.67,11.68 73.15,5.21 77.85,5.21 78.74,4.32 ADCH.3
ADC11  (via drill 0.41)
  Top 0.203: IC3.86 51.8,38.08 52.2,38.48 52.2,41.02 52.7,41.53 52.7,42.42 52.32,42.93 v52.32,44.2
  Bottom 0.203: v52.32,44.2 52.32,42.93 52.7,42.42 52.7,41.53 52.2,41.02 52.2,38.48 51.82,38.1 51.82,26.92 54.86,23.88 54.86,15.62 58.17,12.32 66.8,12.32 73.28,5.84 79.5,5.84 81.28,4.06 ADCH.4
ADC12  (via drill 0.41)
  Top 0.203: IC3.85 52.3,37.95 52.7,38.35 52.7,40.89 53.21,41.4 v53.21,43.31
  Bottom 0.203: v53.21,43.31 53.21,41.4 52.7,40.89 52.7,38.35 52.32,37.97 52.32,27.05 55.37,24 55.37,15.88 58.29,12.95 66.93,12.95 73.53,6.35 79.88,6.35 81.79,4.45 83.44,4.45 83.82,4.06 ADCH.5
ADC13  (via drill 0.41)
  Top 0.203: IC3.84 52.8,37.81 53.21,38.23 53.21,40.77 53.72,41.27 53.72,42.55 54.1,42.93 v54.1,44.2
  Bottom 0.203: v54.1,44.2 54.1,42.93 53.72,42.55 53.72,41.27 53.21,40.77 53.21,38.23 52.83,37.85 52.83,27.18 55.88,24.13 55.88,16.13 58.42,13.59 67.18,13.59 73.91,6.86 80.26,6.86 82.04,5.08 85.22,5.08 86.36,3.94 ADCH.6
ADC14  (via drill 0.41)
  Top 0.203: IC3.83 53.3,37.68 53.72,38.1 53.72,40.51 54.61,41.4 v54.61,42.04
  Bottom 0.203: v54.61,42.04 54.61,41.4 53.72,40.51 53.72,38.1 53.34,37.72 53.34,27.3 56.39,24.26 56.39,16.38 58.55,14.22 67.44,14.22 74.3,7.37 80.64,7.37 82.3,5.71 87.25,5.71 88.9,4.06 ADCH.7
ADC15  (via drill 0.41)
  Top 0.203: IC3.82 53.8,37.54 54.23,37.97 54.23,39.88 v54.61,40.26
  Bottom 0.203: v54.61,40.26 54.23,39.88 54.23,37.97 53.85,37.59 53.85,27.43 56.9,24.38 56.9,16.64 58.67,14.86 67.69,14.86 74.68,7.87 81.03,7.87 82.55,6.35 89.03,6.35 91.44,3.94 ADCH.8
AREF  (via drill 0.41)
  Top 0.203: C3.1 25.53,44.45 24.51,45.47 24.51,49.4 PWMH.8
  Top 0.254: IC3.98 45.8,37.38 45.34,37.85 45.09,37.85 44.45,38.35 v42.09,38.35
  Top 0.305: v28.19,45.85 27.73,45.59 C3.1
  Bottom 0.305: PWMH.8 24.13,50.55 | v28.19,45.85 28.96,45.21 40.51,45.21 41.27,44.45 41.27,39.17 v42.09,38.35
CMP
  Top 0.254: RN5.7 18.02,16.11 18.41,16.51 18.41,16.76 18.54,16.89 19.07,16.89
  Top 0.305: IC5.5 20.74,18.77 C12.2 19.87,16.91 RN5.3 19.07,16.89
D+
  Top 0.406: 6.99,40.64 7.2,40.85 9.06,40.85 10.54,39.37 11.32,39.37 RN2.5 11.61,39.3 12.06,39.75 12.06,40.13 12.45,40.51 12.94,40.51 Z2.2
  Top 0.61: X2.3 6.52,40.17 6.99,40.64
D-
  Top 0.406: 9.53,38.1 9.56,38.1 10.03,37.63 10.03,37.59 10.79,36.83 11.32,36.83 RN2.8 13.06,35.23 Z1.2
  Top 0.61: X2.2 8.53,39.1 9.53,38.1
DTR  (via drill 0.41)
  Top 0.254: v21.97,38.35 IC4.13
  Top 0.305: C7.1 26.04,17.78 v25.78,18.16
  Bottom 0.254: v25.78,18.16 27.18,18.16 27.18,25.4 24.38,28.19 24.38,35.94 22.73,37.59 22.73,37.58 v21.97,38.35 21.08,39.24 UBOOT.1
GATE_CMD
  Top 0.406: T2.3 18.14,24.41 18.41,24.13 18.41,22.86 19.05,22.23 IC5.7
GND  (via drill 0.41)
  Top 0.203: 54.23,35.18 54.3,35.25 IC3.81 54.33,36.35 | 54.3,37.28 54.3,36.38 54.33,36.35 | IC3.32 47.8,21.39 47.88,21.46 52.83,21.46 | IC3.32 | IC3.32 47.8,19.48 46.99,18.67 | 54.33,36.35 54.36,36.32
  Top 0.254: 17.54,37.35 IC4.3 17.54,35.04 19.18,33.4
  Top 0.305: IC2.1 11.81,15.49 IC1.1 | 45.39,35.1 45.29,35.2 IC3.99 | IC3.11 42.86,29.35 42.88,29.36 44.32,29.36 | 44.32,29.36 44.4,29.36 | 56.06,27.86 56.08,27.84 58.81,27.84 | 58.83,27.84 58.82,27.85 IC3.62 58.81,27.84 | 54.3,37.28 55.24,38.23 v55.24,38.86 | 44.32,29.36 44.32,29.34 44.35,29.36 44.42,29.36 | v38.35,29.23 38.61,30.48 | 59.94,27.81 59.92,27.84 58.81,27.84 | v17.27,37.21 IC4.EXP
  Top 0.406: C4.2 39.88,6.48 40.26,6.1 40.26,3.94 POWER.4 | 56.06,27.86 56.01,27.81 v55.88,27.94 | v45.21,33.4 45.21,34.92 45.39,35.1 | v17.27,37.21 17.53,37.21 18.41,38.1
  Top 0.61: v55.88,27.94 55.88,27.81 | 44.42,29.36 v45.09,28.7
  Top 0.813: JP3.1 JP4.1
  Bottom 0.305: GROUND.2 10.16,33.02
  Bottom 0.406: v45.09,28.7 45.09,29.08 45.72,29.72 45.72,33.27 v45.21,33.4 | v55.24,38.86 55.24,37.97 54.48,37.21 | v55.88,27.94 54.48,29.34
  Bottom 0.813: v60.83,31.37 59.87,31.37 58.98,30.48 58.93,30.48 56.39,27.94 v55.88,27.94 | 93.73,7.87 JP3.1
  Bottom 1.016: 25.02,5.71 25.78,6.48 36.96,6.48 37.47,6.1 37.72,6.35 40.64,6.35 | POWER.5 43.18,5.08 41.91,6.35 40.64,6.35 | 40.64,6.35 POWER.4
  Bottom 1.27: 25.02,5.71 20.57,5.71 14.1,11.94 9.2,11.94 X1.3
  other vias: 18.41,26.04 69,20 38.23,21.21 32.64,33.66 87.63,38.61 87.76,20.95 72.49,35.71 24.64,11.68 13.59,13.97 32.64,16 40.77,21.21 18.54,41.66 25.53,24.26 58.29,41.4 77.5,47.8 43.81,40.39 44.7,27.3 48.39,5.67 25.78,3.43 13.21,22.1 24.13,26.54 24.51,43.31 60.83,27.81 58.04,20.45 12.19,28.96 37.72,24.64 77.98,27.69 76.71,18.04 99.81,31.75 79.88,23.88 70.36,23.88 71.63,27.05 18.29,28.83 70.34,32.1 63,20 17.27,32.38 99.81,16.51 66.15,51.44 22.08,50.8 18.29,20.19
  pour Top (isolate 0.305, rank 2): 0.64,52.7 101.6,52.7 101.6,0.64 0.64,0.64 0.64,29.84 10.79,29.84 10.79,46.35 0.64,46.35
  pour Bottom (isolate 0.356, rank 2): 0.64,52.7 101.6,52.7 102.23,52.07 102.23,0.64 1.27,0.64 0.64,1.27 0.64,29.84 10.79,29.84 10.79,46.35 0.64,46.35
M8RXD
  Top 0.254: IC4.9 23.72,36.35 25.78,34.29 25.78,31.5 26.54,30.73 27.25,30.73 RN4.7
M8TXD
  Top 0.254: RN4.8 26.47,29.91 25.02,31.37 25.02,34.16 23.5,35.69 20.15,35.69 IC4.8
MISO2
  Top 0.254: IC4.17 20.04,41.3 19.68,41.66 19.68,42.67 18.8,43.56 17.65,43.56 17.02,44.2 17.02,48.13 17.53,48.64 19.05,48.64 20.19,47.5 ICSP1.1
MOSI2
  Top 0.254: IC4.16 20.93,39.85 21.21,40.13 21.21,41.02 20.19,42.04 20.19,43.05 ICSP1.4
N$2
  Top 0.254: RN3.4 27.76,38.17 27.94,38.35 27.94,41.66 28.19,41.91 L.A
N$3  (via drill 0.41)
  Top 0.203: 77.22,37.08 ON.A | v80.14,46.74 80.01,46.74 79.12,45.85 60.96,45.85 v60.07,46.74
  Top 0.254: v30.48,46.74 30.99,46.23 30.99,42.16 29.97,41.15 29.97,39.5 29.46,38.99 28.63,38.99 RN3.6 | 77.22,37.08 77.22,37.37 v75.96,38.62
  Bottom 0.203: v75.96,38.62 80.14,42.8 v80.14,46.74 | v60.07,46.74 57.15,46.74 56.77,47.12 51.82,47.12 50.93,46.23 44.45,46.23 43.94,46.74 v30.48,46.74
N$54
  Top 0.254: RN4.4 28.61,33.82 RX.A
N$55
  Top 0.254: RN4.3 28.98,31.52 30.61,33.15 30.61,35.31 TX.A
PA0
  Top 0.203: IC3.78 55.8,37.89 56.26,38.35 56.26,43.18 58.42,45.34 90.3,45.34 93.22,48.26 XIOH.16
PA1
  Top 0.203: IC3.77 56.3,37.63 56.77,38.1 56.77,42.93 58.67,44.83 90.81,44.83 92.96,46.99 95.25,46.99 XIOH.15
PA2
  Top 0.203: XIOH.14 92.71,45.72 91.31,44.32 58.93,44.32 57.28,42.67 57.28,37.85 56.8,37.37 IC3.76
PA3
  Top 0.203: XIOH.13 95.25,44.45 92.2,44.45 91.57,43.81 61.98,43.81 61.34,43.18 61.34,39.26 59.44,37.35 59.44,34.67 59.11,34.35 IC3.75
PA4
  Top 0.203: IC3.74 59.75,33.85 59.94,34.04 59.94,37.23 61.85,39.13 61.85,42.8 62.36,43.31 92.58,43.31 92.71,43.18 XIOH.12
PA5
  Top 0.203: IC3.73 60.02,33.35 60.45,33.78 60.45,36.97 62.36,38.88 62.36,42.29 62.87,42.8 91.57,42.8 92.46,41.91 95.25,41.91 XIOH.11
PA6
  Top 0.203: IC3.72 60.28,32.85 60.96,33.53 60.96,36.72 62.87,38.62 62.87,41.91 63.25,42.29 90.81,42.29 92.46,40.64 XIOH.10
PA7
  Top 0.203: IC3.71 60.54,32.35 61.47,33.27 61.47,36.47 63.37,38.37 63.37,41.4 63.75,41.78 90.04,41.78 92.46,39.37 95.25,39.37 XIOH.9
PB0  (via drill 0.41)
  Top 0.203: IC3.19 45.39,25.35 v45.21,25.4 | v49.4,11.56 50.04,11.56 50.29,11.81 92.33,11.81 92.71,11.43 95.25,11.43 XIOL.1
  Bottom 0.203: v45.21,25.4 45.34,25.4 48.64,22.1 48.64,12.19 v49.4,11.56
PB1  (via drill 0.41)
  Top 0.203: IC3.20 41.19,24.85 v40.89,25.15 | XIOL.2 92.71,10.16 91.57,11.3 75.18,11.3 74.8,10.92 v73.91,10.92 73.53,11.3 50.55,11.3 49.78,10.54 49.48,10.54 v49.23,10.29
  Bottom 0.203: v40.89,25.15 44.2,25.15 45.97,23.37 46.61,23.37 48.13,21.84 48.13,10.92 48.77,10.29 v49.23,10.29 | 63.75,27.94 64.69,27 64.69,18.31 67,16
  Bottom 0.254: 63.75,27.94 ICSP.3
  Bottom 0.305: 67,16 68.83,16 v73.91,10.92
PB2  (via drill 0.41)
  Top 0.203: IC3.21 41.24,24.35 41.02,24.13 v39.88,24.13 | XIOL.3 97.79,11.43 97.79,9.53 97.16,8.89 92.71,8.89 90.81,10.79 77.47,10.79 76.83,10.16 v75.82,10.16 75.69,10.03 73.66,10.03 72.9,10.79 51.34,10.79 v50.67,10.12
  Bottom 0.203: v39.88,24.13 41.02,24.13 41.66,24.64 44.07,24.64 45.85,22.86 46.35,22.86 47.62,21.59 47.62,10.54 48.77,9.4 49.95,9.4 v50.67,10.12 | ICSP.4 66.42,27.94 67.31,27.05
  Bottom 0.254: 67.31,27.05 67.31,24.77 65.66,23.11 65.66,19.11 67.49,17.27 | 74.8,12.45 75.82,11.3 v75.82,10.16
  Bottom 0.305: 67.49,17.27 69.98,17.27 74.8,12.45
PB3  (via drill 0.41)
  Top 0.203: IC3.22 44.35,23.85 44.58,23.62 v44.58,22.99 | v81.03,8.76 81.03,9.14 80.01,10.16 77.85,10.16 77.09,9.4 73.53,9.4 72.64,10.29 52.58,10.29 50.93,8.64 v49.02,8.64
  Bottom 0.203: v81.03,8.76 81.15,8.76 82.93,6.99 89.66,6.99 91.19,5.46 96.9,5.46 98.04,6.6 98.04,10.54 97.16,11.43 95.25,11.43 XIOL.4 | v44.58,22.99 45.09,22.99 45.72,22.35 46.1,22.35 47.12,21.34 47.12,10.29 48.77,8.64 v49.02,8.64 | ICSP.1 65.1,29.01 65.1,18.72 67.18,16.64
  Bottom 0.254: v81.03,8.76 81.03,9.27 80.39,9.91 78.11,9.91 77.34,9.14 75.56,9.14 74.93,9.78 74.93,11.18 74.17,11.94 | 69.47,16.64 67.18,16.64
  Bottom 0.305: 74.17,11.94 69.47,16.64
PB4
  Top 0.203: PWMH.3 36.83,49.66 35.31,48.13 35.31,24.38 36.32,23.37 42.93,23.37 42.9,23.35 IC3.23
PB5
  Top 0.203: IC3.24 36.08,22.85 34.8,24.13 34.8,48.51 34.29,49.02 PWMH.4
PB6
  Top 0.203: IC3.25 42.92,22.35 42.93,22.35 35.81,22.35 34.29,23.88 34.29,47.62 31.75,50.16 PWMH.5
PB7  (via drill 0.41)
  Top 0.203: IC3.26 44.22,20.34 44.09,20.22 37.19,20.22 33.78,23.62 33.78,40.13 33.15,40.77 v30.86,40.77
  Top 0.254: v30.86,40.77 30.86,39.62 29.46,38.23 28.67,38.23 RN3.5
  Bottom 0.254: PWMH.6 29.21,49.53 26.67,46.99 26.67,45.09 28.57,43.18 29.84,43.18 30.48,42.55 30.48,41.15 v30.86,40.77
PC0
  Top 0.203: IC3.53 61.49,23.35 62.74,22.1 81.03,22.1 88.14,29.21 95.25,29.21 XIOH.1
PC1
  Top 0.203: IC3.54 61.75,23.85 62.87,22.61 80.52,22.61 88.39,30.48 XIOH.2
PC2
  Top 0.203: IC3.55 62.01,24.35 63.12,23.24 68.33,23.24 70.1,25.02 82.04,25.02 88.77,31.75 95.25,31.75 XIOH.3
PC3
  Top 0.203: IC3.56 62.28,24.85 63.37,23.75 68.2,23.75 69.98,25.53 81.53,25.53 89.03,33.02 XIOH.4
PC4
  Top 0.203: IC3.57 61.92,25.35 63.04,26.47 67.36,26.47 69.98,29.08 83.82,29.08 89.03,34.29 95.25,34.29 XIOH.5
PC5
  Top 0.203: IC3.58 61.66,25.85 62.69,26.87 67,26.87 69.85,29.72 83.57,29.72 89.41,35.56 XIOH.6
PC6
  Top 0.203: IC3.59 61.52,26.35 62.48,27.3 62.48,28.7 62.79,29.01 67.89,29.01 69.24,30.35 83.19,30.35 89.66,36.83 95.25,36.83 XIOH.7
PC7
  Top 0.203: IC3.60 61.39,26.85 61.98,27.43 61.98,28.83 62.56,29.41 67.61,29.41 69.06,30.86 69.34,30.86 69.85,30.86 82.68,30.86 89.92,38.1 XIOH.8
PD7
  Top 0.203: XIOL.16 88.01,27.94 81.66,21.59 60.3,21.59 60.3,21.57 59.69,20.95 59.69,20.57 58.17,19.05 58.04,19.05 57.4,18.41 56.9,18.41 56.8,18.51 IC3.50
PE0  (via drill 0.41)
  Top 0.203: PWML.1 61.47,48.77 59.69,48.77 58.04,47.12 52.83,47.12 51.18,45.47 45.59,45.47 44.58,44.45 41.91,44.45 40.39,42.93 40.39,36.7 v40.64,36.45 42.16,34.92 43.69,34.92 43.94,34.67 43.94,34.04 43.75,33.85 IC3.2
  Top 0.254: v30.61,37.97 30.54,37.9 30.54,36.12 31.11,35.56 31.11,32.38 29.46,30.73 28.63,30.73 RN4.2
  Bottom 0.203: v30.61,37.97 31.37,37.85
  Bottom 0.254: 31.37,37.85 39.24,37.85 v40.64,36.45
PE1  (via drill 0.41)
  Top 0.203: v40.39,35.18 39.88,35.69 39.88,43.05 41.91,45.09 44.45,45.09 45.34,45.97 50.8,45.97 52.45,47.62 57.78,47.62 59.44,49.28 60.96,49.28 PWML.2 | v39.62,33.53 39.88,33.27 39.95,33.35 IC3.3
  Top 0.254: RN4.1 29.91,29.91 31.62,31.62 31.62,36.32 v31.5,36.7
  Bottom 0.203: v40.39,35.18 40.39,34.29 v39.62,33.53
  Bottom 0.254: v31.5,36.7 38.73,36.7 v40.39,35.18
PE3  (via drill 0.41)
  Top 0.203: IC3.5 39.54,32.35 38.86,33.02 38.86,43.31 41.91,46.35 44.2,46.35 45.09,47.24 49.28,47.24 v49.4,47.37
  Bottom 0.203: v49.4,47.37 49.4,47.62 50.8,49.02 50.8,50.55 50.67,50.67 PWML.6
PE4
  Top 0.203: IC3.6 39.02,31.85 38.35,32.51 38.35,43.43 41.91,46.99 43.94,46.99 44.7,47.75 46.99,47.75 47.37,48.13 57.28,48.13 58.42,49.28 PWML.3
PE5
  Top 0.203: IC3.7 42.78,31.35 42.55,31.37 38.73,31.37 37.85,32.26 37.85,43.56 41.91,47.62 43.94,47.62 44.58,48.26 46.61,48.26 46.99,48.64 55.37,48.64 55.88,49.15 PWML.4
PG0  (via drill 0.41)
  Top 0.203: IC3.51 58.8,21.84 v59.05,21.46 | XIOL.13 95.25,24.13 88.14,24.13 84.07,20.07 71.75,20.07 71.25,19.56 70.36,18.67 70.1,18.41 59.69,18.41 59.44,18.67 v59.05,18.67
  Bottom 0.203: v59.05,18.67 v59.05,21.46
PG1  (via drill 0.41)
  Top 0.203: IC3.52 60.44,22.85 v60.83,22.48 | XIOL.14 88.14,25.4 83.31,20.57 71.12,20.57 69.6,19.05 60.33,19.05 59.94,19.43 v59.94,19.56
  Bottom 0.203: v59.94,19.56 60.58,19.56 61.34,20.32 61.34,21.97 v60.83,22.48
PG2  (via drill 0.41)
  Top 0.203: IC3.70 59.8,31.85 59.92,31.73 59.92,29.49 v60.33,29.08 | v60.58,20.7 61.09,20.7 61.47,21.08 82.55,21.08 88.14,26.67 95.25,26.67 XIOL.15
  Bottom 0.203: v60.58,20.7 60.2,20.7 59.94,20.95 59.94,28.57 v60.33,29.08
PG5  (via drill 0.41)
  Top 0.203: IC3.1 42.73,34.35 42.67,34.29 40.13,34.29 39.37,35.05 39.37,43.18 41.91,45.72 44.32,45.72 45.09,46.48 50.04,46.48 v50.67,47.12
  Bottom 0.203: PWML.5 53.34,48.64 52.58,47.88 51.44,47.88 v50.67,47.12
PH3
  Top 0.203: IC3.15 37.42,27.35 37.34,27.43 37.34,43.69 41.91,48.26 43.81,48.26 44.32,48.77 46.23,48.77 PWML.7
PH4
  Top 0.203: IC3.16 37.16,26.85 36.83,27.18 36.83,43.81 41.91,48.9 43.56,48.9 45.72,51.05 PWML.8
PH5
  Top 0.203: IC3.17 36.9,26.35 36.32,26.92 36.32,45.59 39.62,48.9 40.64,48.9 41.91,50.16 PWMH.1
PH6
  Top 0.203: PWMH.2 39.37,49.91 35.81,46.35 35.81,26.67 36.58,25.91 42.67,25.91 42.73,25.85 IC3.18
PL0
  Top 0.203: 49.28,20.3 49.28,14.22 51.18,12.32 90.3,12.32 91.95,13.97 95.25,13.97 XIOL.5
  Top 0.254: IC3.35 49.3,20.32 49.28,20.3
PL1
  Top 0.203: IC3.36 49.8,14.46 51.44,12.83 89.53,12.83 91.95,15.24 XIOL.6
PL2
  Top 0.203: 50.29,20.3 50.29,14.99 51.94,13.34 88.9,13.34 92.08,16.51 95.25,16.51 XIOL.7
  Top 0.254: IC3.37 50.27,20.32 50.29,20.3
PL3
  Top 0.203: IC3.38 50.8,15.49 52.45,13.84 88.27,13.84 92.2,17.78 XIOL.8
PL4
  Top 0.203: 51.31,20.22 51.31,15.75 52.7,14.35 87.63,14.35 92.33,19.05 95.25,19.05 XIOL.9
  Top 0.254: IC3.39 51.3,20.28 51.33,20.24 51.31,20.22
PL5
  Top 0.203: IC3.40 51.8,16.02 52.96,14.86 87,14.86 92.46,20.32 XIOL.10
PL6
  Top 0.203: 52.32,20.24 52.32,16.51 53.47,15.37 86.49,15.37 92.71,21.59 95.25,21.59 XIOL.11
  Top 0.254: IC3.41 52.3,20.32 52.27,20.3 52.32,20.24
PL7
  Top 0.203: IC3.42 52.8,17.05 53.98,15.88 85.72,15.88 92.71,22.86 XIOL.12
PWRIN
  Top 1.27: D1.A 15.44,12.06 X1.2
RD+
  Top 0.254: IC4.29 13.71,37.85 13.59,37.97 13.59,38.61 13.53,39.3 RN2.4
RD-
  Top 0.254: IC4.30 13.86,37.35 13.59,37.08 13.59,36.96 13.5,36.87 12.77,36.87 RN2.1
RESET  (via drill 0.41)  (1 unrouted)
  Top 0.254: 46.8,19.44 46.53,19.18 44.2,19.18 43.69,19.68 | 64.72,24.31 68.12,24.31 69.85,26.04 78.74,26.04 v80.01,27.3
  Top 0.305: POWER.1 33.02,7.24 v31.5,9.4 | 46.8,19.44 IC3.30 | ICSP.5 64.72,24.31 | RN1.1 79.97,39.08 80.9,40.01 82.55,40.01 82.68,40.13 84.2,40.13 84.45,39.88 84.45,33.78 82.8,32.13 v80.01,32.13 RESET.4 | 43.69,19.68 35.69,19.68 34.29,18.29 34.29,17.78 33.66,17.14 31.11,17.14 29.21,15.24 RESET-EN.2 | C7.2 28.79,17.36 27.94,16.51 27.3,16.51 27.3,15.37 RESET-EN.1 RESET-EN.2 | RESET-EN.2 28.57,15.11 28.57,13.55 C1.1 28.57,13.12 28.57,12.7 28.11,12.23 27.09,12.23 v26.54,11.68
  Top 0.406: v46.85,8.26 47.88,8.26 48.51,7.62 49.53,7.62 49.78,7.87 51.05,7.87 52.96,9.78 72.14,9.78 73.28,8.64 78.49,8.64 v78.61,8.76
  Bottom 0.254: 63.75,25.27 64.26,24.77 64.26,17.78 66.67,15.37
  Bottom 0.305: v78.61,8.76 78.11,8.76 77.98,8.64 74.93,8.64 68.2,15.37 66.67,15.37 | 63.75,25.27 ICSP.5 | v46.85,8.26 46.1,9.02 32,9.02 v31.5,9.4 28.83,9.4 v26.54,11.68 | v80.01,27.3 v80.01,32.13
RESET2  (via drill 0.41)
  Top 0.305: v16.95,41.59 16.51,41.15 16.51,40.43 IC4.24 | v16.95,41.59 17.02,41.66 | ICSP1.5 14.1,45.85 14.1,44.32 16.26,42.16 16.38,42.16 v16.95,41.59 | RN5.8 16.58,15.31 v16.51,15.24
  Bottom 0.305: v16.95,41.59 16.64,41.27 16.64,41.15 22.86,34.92 22.86,29.84 20.95,27.94 20.95,25.4 16.76,21.21 16.76,15.24 v16.51,15.24
RXD1  (via drill 0.41)
  Top 0.203: IC3.45 54.33,20.35 54.36,20.32 54.36,18.29 55.3,17.35 71.96,17.35 v72.64,17.91
  Bottom 0.203: COMMUNICATION.3 81.28,42.67 74.17,35.56 74.17,19.56 v72.64,17.91
RXD2  (via drill 0.41)
  Top 0.203: IC3.12 41.04,28.85 v41.02,28.83
  Bottom 0.203: v41.02,28.83 41.02,30.1 42.67,31.75 42.67,37.08 43.43,37.85 43.43,38.99 42.67,39.75 42.67,43.94 43.94,45.21 51.18,45.21 51.94,45.97 55.63,45.97 56.26,45.34 60.45,45.34 63.5,48.39 63.96,48.39 64.85,49.28 67.13,49.28 68.02,48.39 73.66,48.39 74.04,48.77 75.69,48.77 76.2,49.28 COMMUNICATION.5
RXD3  (via drill 0.41)
  Top 0.203: COMMUNICATION.7 71.12,49.28 70.61,48.77 67.69,48.77 66.8,47.75 v66.8,47.37 | v55.75,29.72 55.75,29.46 56.9,28.32 58.8,28.32 IC3.63
  Bottom 0.203: v66.8,47.37 66.8,46.99 55.45,35.51 55.45,33.6 56.13,32.89 56.26,32.89 56.77,32.38 56.77,31.11 56.39,30.73 56.01,30.73 55.63,30.35 55.63,29.84 v55.75,29.72
RXL
  Top 0.254: IC4.10 24.24,36.85 RX.C
SCK2
  Top 0.254: IC4.15 21.19,39.35 21.84,40.01 21.84,41.15 20.7,42.29 20.7,43.31 19.56,44.45 19.56,46.23 ICSP1.3
SCL  (via drill 0.41)
  Top 0.203: IC3.43 53.3,17.31 54.23,16.38 74.68,16.38 75.06,16.76 v75.31,16.89
  Top 0.254: 80.54,37.23 80.64,37.34 80.64,38.86
  Top 0.305: v81.41,39.12 80.9,39.12 80.64,38.86 | 80.54,37.23 RN1.2
  Bottom 0.203: v75.31,16.89 75.18,17.02 75.18,34.29 80.01,39.12 v81.41,39.12 81.41,40.77 83.82,43.18 83.82,46.99 85.72,48.9 86.36,48.9 COMMUNICATION.1
SDA  (via drill 0.41)
  Top 0.203: v74.04,17.65 73.28,16.89 54.48,16.89 53.85,17.53 53.85,19.94 53.8,20.04 53.8,20.14 IC3.44
  Top 0.305: v78.74,38.99 78.74,36.83 79.12,36.45 79.95,36.45 RN1.3
  Bottom 0.203: v74.04,17.65 74.04,18.67 74.68,19.3 74.68,34.92 v78.74,38.99 82.55,42.8 82.55,48.26 83.82,49.53 COMMUNICATION.2
TXD1  (via drill 0.41)
  Top 0.203: IC3.46 54.8,20.26 54.86,20.19 54.86,18.67 55.63,17.91 70.74,17.91 v72.01,19.18
  Bottom 0.203: COMMUNICATION.4 78.74,42.55 73.66,37.47 73.66,20.07 72.64,19.18 v72.01,19.18
TXD2  (via drill 0.41)
  Top 0.203: IC3.13 41.81,28.35 41.4,27.94 39.88,27.94 39.75,28.07 v39.75,28.83
  Bottom 0.203: v39.75,28.83 39.75,29.59 42.16,32 42.16,37.21 42.93,37.97 42.93,38.86 42.16,39.62 42.16,44.2 43.69,45.72 51.05,45.72 51.94,46.61 55.88,46.61 56.52,45.97 60.45,45.97 63.37,48.9 63.88,48.9 64.77,49.78 67.21,49.78 68.1,48.9 73.15,48.9 73.66,49.53 COMMUNICATION.6
TXD3  (via drill 0.41)
  Top 0.203: COMMUNICATION.8 67.06,50.8 66.42,50.16 66.42,48.51 v65.28,47.37 | IC3.64 58.66,28.85 58.55,28.83 57.66,28.83 57.28,29.21 57.28,30.35 v55.75,31.88
  Bottom 0.203: v65.28,47.37 65.28,46.23 54.97,35.89 54.97,32.66 v55.75,31.88
TXL
  Top 0.254: IC4.11 26.28,37.35 TX.C
UGND
  Top 0.305: IC4.28 15.12,38.35 14.61,38.35 14.35,38.61
  Top 0.61: L1.1 11.01,43.56 C10.2 11.09,43.14 11.86,42.34 13.77,42.34 14.35,41.78 14.35,38.61
  Top 0.813: X2.4 6.5,36.83 5.08,36.83 4.45,37.47 4.45,40.51 7.75,43.81 8.76,43.81 9.27,44.32 9.27,45.13 L1.1
  Bottom 0.813: X2.4 6.52,36.53 GROUND.1
USBVCC
  Top 0.305: IC4.31 14.37,36.85 14.22,36.7
  Top 0.406: 14.22,36.7 14.22,34.92 12.95,33.66 12.7,33.66 10.16,31.11 10.16,28.57 12.06,26.67 12.06,25.38
  Top 0.61: F1.1 8.48,25.4 T2.1 12.06,25.38 14.37,25.38 C8.1
USHIELD  (via drill 0.41)
  Top 0.813: X2.P$2 3.81,33.02 5.08,33.02 5.71,33.66 9.79,33.66 Z1.1 | Z2.1 10.18,41.26 10.05,41.26 9.65,41.66 v9.65,42.67 | L1.2 4.92,45.21 X2.P$1
  Bottom 0.813: v9.65,42.67 5.49,42.67 X2.P$1
  Bottom 1.27: X2.P$2 3.81,33.02 1.91,34.92 1.91,41.27 3.81,43.18 X2.P$1
VIN  (via drill 0.41)
  Top 0.203: IC2.3 11.77,20.06 IC1.3
  Top 0.305: RN5.6 16.91,16.91 16.51,16.51 14.61,16.51
  Top 0.406: 17.78,13.97 17.74,14.01
  Top 0.61: IC2.3 12.32,20.06 14.61,17.78 C2.1 14.61,17.57 14.61,16.51 14.61,15.24 15.88,13.97 17.78,13.97 19.68,13.97 20.61,13.04 D1.C
  Top 1.27: v24,7.37 23.25,8.12 PC1.+ 20.32,11.13 D1.C
  Bottom 1.27: v24,7.37 24.38,7.87 43.81,7.87 45.72,5.97 POWER.6
VUCAP
  Top 0.305: IC4.27 15.12,38.85 15.11,38.86 15.11,42.16 13.84,43.43 13.17,43.43 C10.1
XT1
  Top 0.254: Y2.3 17.29,29.99 16.51,29.21 16.51,28.36 C16.1 R2.1
  Top 0.305: Y2.3 Q1.2 15.75,31.88 15.24,32.38 15.24,33.4 R4.2
XT1R
  Top 0.305: IC4.1 16.54,33.88 R4.1
XT2
  Top 0.254: R2.2 C17.1 20.74,28.79 19.29,30.24 Y2.1 19.29,31.89 17.78,33.66 17.78,34.04 17.02,34.8 17.02,35.78 IC4.2
  Top 0.305: Y2.1 Q1.1
XTAL1
  Top 0.203: R1.1 R3.2
  Top 0.254: Q2.2 Y1.3 37.83,13.61 38.73,12.7 39.59,12.7 C14.2 R1.1
XTAL1R
  Top 0.203: IC3.34 48.8,18.8 47.53,17.53 42.55,17.53 41.91,16.89 R3.1
XTAL2
  Top 0.203: IC3.33 48.3,19.18 47.05,17.93 43.41,17.93 43.05,18.29 41.78,18.29 40.39,16.89 C15.2
  Top 0.254: Q2.1 Y1.1 37.83,15.61 38.73,16.51 39.59,16.51 C15.2 R1.2
XVCC
  Top 0.61: F1.2 2.5,25.45 1.52,26.42 1.52,34.54 1.91,34.92 6.59,34.92 X2.1
(copper drawn outside any net)
  shapes: Top area x1

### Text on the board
Top: Arduino Mega 2560 Reference Design | Reference Designs ARE PROVIDED "AS IS" AND "WITH ALL FAULTS. Arduino DISCLAIMS ALL OTHER WARRANTIES, EXPRESS OR IMPLIED, | REGARDING PRODUCTS, INCLUDING BUT NOT LIMITED TO, ANY IMPLIED WARRANTIES OF MERCHANTABILITY OR FITNESS FOR A PARTICULAR PURPOSE | Arduino may make changes to specifications and product descriptions at any time, without notice. The Customer must not | rely on the absence or characteristics of any features or instructions marked "reserved" or "undefined." Arduino reserves | these for future definition and shall have no responsibility whatsoever for conflicts or incompatibilities arising from future changes to them. | The product information on the Web Site or Materials is subject to change without notice. Do not finalize a design with this information.
tPlace: 9 | 8 | 7 | 6 | 5 | 4 | 3 | 2 | 1 | 0 | 22 | 14 | 15 | 16 | 17 | 18 | 19 | 20 | 21 | 13 | 12 | 11 | 10 | 24 | 26 | 28 | 30 | 31 | 32 | 33 | 34 | 35 | 36 | 37 | 38 | 39 | 40 | 41 | 42 | 43 | www.arduino.cc | 44 | 45 | 46 | 47 | TM | 48 | 49 | 50 | 51 | 52 | 53 | 0 | 1 | 2 | 3 | 4 | 5 | 6 | 7 | 8 | 9 | 10 | 11 | 12 | 13 | 14 | 15
tNames: M.Banzi | 5V | D.Cuartielles | T.Igoe | MADE IN | G.Martino | D.Mellis | ITALY | GND | AREF | PWM | TX | RX | TX3 | RX3 | TX2 | RX2 | TX1 | RX1 | SDA | SCL | 1 | DIGITAL | Arduino | MEGA 2560 | ANALOG IN | GND | MEGAXL | RESET | 3V3 | 5V | GND | VIN
bNames: MADE IN | designed by | ITALY | tinker it
ReferenceLC: L | TX | RX | PC1 | PC2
